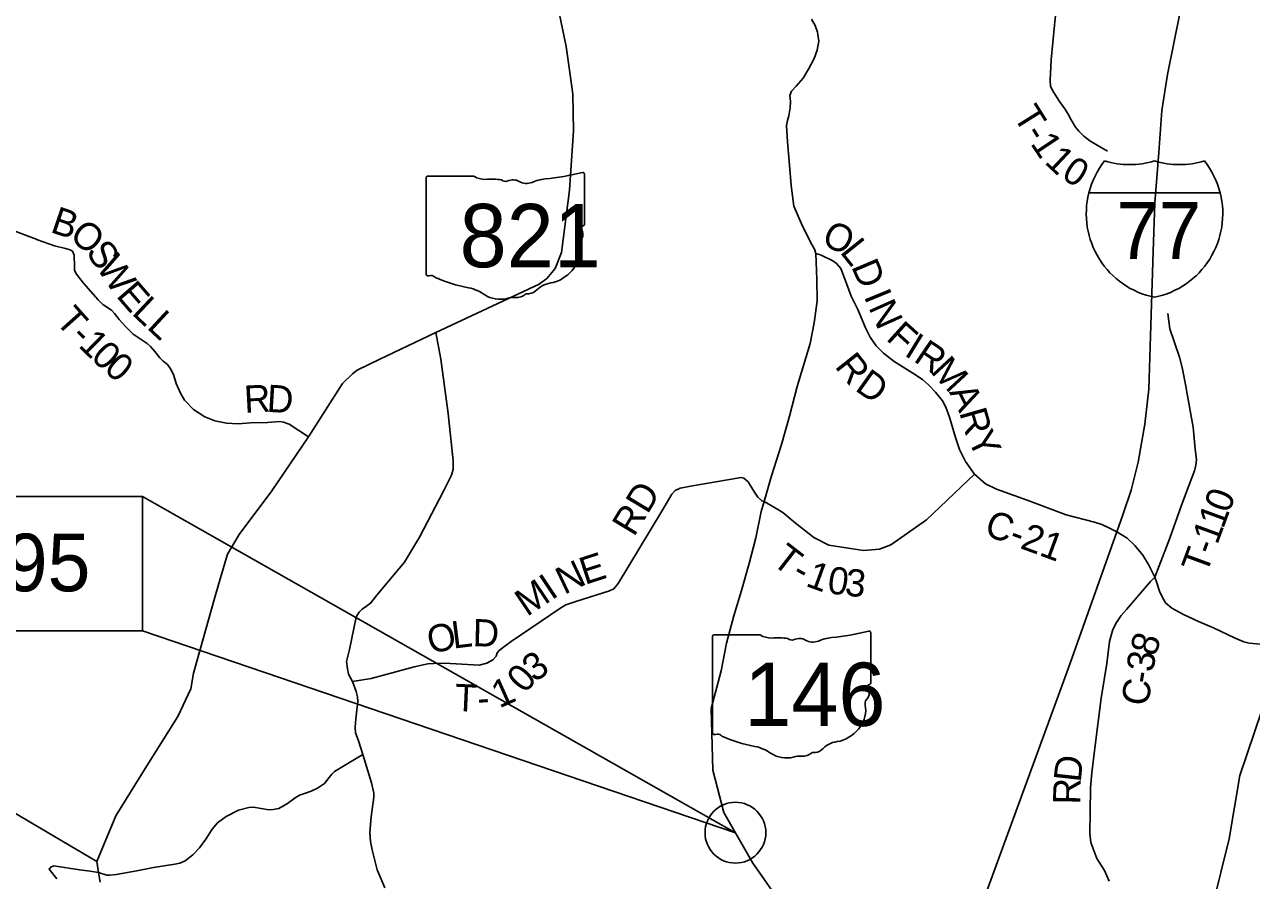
# Model space of a CAD drawing. Extents: x -22 to 431, y -18 to 160.
# Drawn here: x 322.427 to 324.981, y 154.927 to 156.71 of the extents above; entities that cross this region are included whole.
import ezdxf

# ---------------------------------------------------------------- set-up
doc = ezdxf.new("R2010")
doc.units = 0
for name, color, linetype in [('GM_X_Adjacent_County', 7, 'Continuous'), ('GM_X_Adjacent_County_Text', 7, 'Continuous'), ('GM_X_Airport_Location_Class_2', 7, 'Continuous'), ('GM_X_City_Street', 7, 'Continuous'), ('GM_X_City_Street_Text', 7, 'Continuous'), ('GM_X_County_Road', 7, 'Continuous'), ('GM_X_County_ROW', 7, 'Continuous'), ('GM_X_Minor_Lake', 7, 'Continuous'), ('GM_X_Minor_River_Text', 7, 'Continuous'), ('GM_X_Rail_Line', 7, 'Continuous'), ('GM_X_Rail_Line_Text', 7, 'Continuous'), ('GM_X_Section', 7, 'Continuous')]:
    doc.layers.add(name, color=color, linetype=linetype)

msp = doc.modelspace()

# ---------------------------------------------------------------- linework, layer by layer
at = {"layer": 'GM_X_Adjacent_County'}
msp.add_circle((323.9069, 155.0269), 0.0633, dxfattribs=at)
at = {"layer": 'GM_X_Adjacent_County_Text'}
for points in [[(324.0743, 156.2336), (324.0837, 156.2305), (324.11, 156.2181), (324.1175, 156.2127), (324.1265, 156.2024), (324.1379, 156.1712), (324.1482, 156.1446), (324.1615, 156.1168), (324.1774, 156.0783), (324.1874, 156.0593), (324.2001, 156.0413), (324.215, 156.0256), (324.2372, 156.0084), (324.2762, 155.9841), (324.2965, 155.971), (324.3089, 155.9599), (324.3238, 155.9442), (324.3377, 155.9266), (324.3447, 155.9133), (324.3528, 155.8927), (324.3652, 155.8498), (324.3737, 155.8254), (324.3859, 155.7999), (324.4049, 155.774), (324.4278, 155.7536), (324.4507, 155.7424), (324.514, 155.7194), (324.5957, 155.6891), (324.6546, 155.6737), (324.6696, 155.6686), (324.6832, 155.6624), (324.7007, 155.6534), (324.7226, 155.6405), (324.7384, 155.6251), (324.7552, 155.6053), (324.7671, 155.5858), (324.78, 155.5591)], [(323.1766, 154.9118), (323.1612, 154.9492), (323.1507, 154.9912), (323.1471, 155.0086), (323.1455, 155.0276), (323.1483, 155.0598), (323.1537, 155.1008), (323.154, 155.1092), (323.1489, 155.1308), (323.1307, 155.1894), (323.1272, 155.2027), (323.121, 155.2204), (323.1156, 155.2348), (323.1152, 155.2454), (323.1155, 155.2564), (323.1187, 155.283), (323.1205, 155.2993), (323.1197, 155.3099), (323.1173, 155.3209), (323.1096, 155.3421), (323.1015, 155.3568), (323.0993, 155.3684), (323.0971, 155.3836), (323.1031, 155.4086), (323.1174, 155.4755), (323.1189, 155.4797), (323.1231, 155.4861), (323.13, 155.4925), (323.1384, 155.4985), (323.1479, 155.5056), (323.1605, 155.5218), (323.2068, 155.577), (323.2179, 155.5906), (323.2487, 155.6422), (323.2992, 155.7384), (323.3154, 155.7716), (323.3189, 155.7841), (323.3191, 155.8015), (323.3088, 155.9002), (323.2933, 156.0129), (323.2832, 156.0685)], [(324.78, 155.5591), (324.7709, 155.5498), (324.725, 155.4964), (324.7212, 155.492)], [(324.78, 155.5591), (324.7845, 155.547), (324.79, 155.5302), (324.7951, 155.5181), (324.8026, 155.5055), (324.8157, 155.4944), (324.8401, 155.4816), (324.8714, 155.4669), (324.9022, 155.4537), (324.9477, 155.4324), (324.9658, 155.4247), (324.9768, 155.4219), (325.0005, 155.4194), (325.0206, 155.4181), (325.0376, 155.4152), (325.0628, 155.4078), (325.0922, 155.3992), (325.1095, 155.3918), (325.1197, 155.3871), (325.1266, 155.3827), (325.1334, 155.3754), (325.141, 155.3672), (325.1441, 155.3573), (325.1469, 155.3484)], [(324.7212, 155.492), (324.7211, 155.4919), (324.7101, 155.4791), (324.7001, 155.4648), (324.6928, 155.4501), (324.6857, 155.4251), (324.6803, 155.3793), (324.6681, 155.3072), (324.6555, 155.2027), (324.6492, 155.1514), (324.6464, 155.1202), (324.6457, 155.0694), (324.6446, 155.025), (324.6472, 155.0064), (324.6591, 154.9729), (324.6751, 154.9478), (324.6853, 154.9259)]]:
    msp.add_lwpolyline(points, dxfattribs=at)
at = {"layer": 'GM_X_Airport_Location_Class_2'}
for p, q in [((323.2627, 156.3907), (323.2627, 156.1906)), ((323.3625, 156.3941), (323.266, 156.3941)), ((323.5923, 156.2944), (323.5923, 156.3991)), ((323.5923, 156.2944), (323.5923, 156.2944)), ((323.8589, 155.4353), (323.8589, 155.2351)), ((323.9587, 155.4387), (323.8621, 155.4387)), ((324.1885, 155.339), (324.1885, 155.4437)), ((324.1885, 155.339), (324.1885, 155.339))]:
    msp.add_line(p, q, dxfattribs=at)
for centre, major_axis, start_param, end_param in [((323.4749, 156.6669), (0.3495, 0), 4.814394, 5.042369), ((323.5886, 156.3995), (0.00367, 0), 6.141152, 7.989035), ((323.2665, 156.3911), (0.00382, 0), 1.712693, 3.28349), ((323.3855, 156.4173), (0.037, 0), 4.042523, 4.731795), ((323.3977, 156.2818), (0.133, 0), 1.404758, 1.657858), ((323.4279, 156.3921), (0.0107, 0), 3.836095, 5.185415), ((323.4436, 156.369), (0.0222, 0), 0.950623, 2.079405), ((323.4723, 156.4007), (0.0267, 0), 4.081561, 5.145723), ((323.5195, 156.333), (0.0703, 0), 1.699011, 2.107814), ((323.5915, 156.2867), (0.00568, 0), 1.883978, 3.671073), ((323.5553, 156.2735), (0.0341, 0), 5.934695, 6.695948), ((323.5884, 156.294), (0.00393, 0), 5.05454, 6.418171), ((323.4945, 156.2373), (0.0874, 0), 5.101752, 6.440018), ((323.6054, 156.2506), (0.0248, 0), 2.387724, 3.262537), ((323.2665, 156.1901), (0.00385, 0), 3.00124, 4.508301), ((323.2671, 156.2106), (0.0294, 0), 4.665946, 4.897461), ((323.2731, 156.179), (0.0106, 0), 0.519207, 1.627899), ((323.4069, 156.3588), (0.2524, 0), 4.195997, 4.488961), ((323.5313, 156.1344), (0.0479, 0), 1.647645, 2.488434), ((323.3317, 156.1006), (0.079, 0), 0.823519, 1.323587), ((323.4171, 156.178), (0.0501, 0), 4.026481, 4.996735), ((323.4497, 156.163), (0.0267, 0), 4.691044, 5.507374), ((323.4739, 156.1436), (0.00752, 0), 1.147584, 2.315152), ((323.4707, 156.1712), (0.0282, 0), 4.937069, 5.64225), ((323.4461, 156.1088), (0.0412, 0), 1.495662, 1.94098), ((323.8627, 155.4357), (0.00382, 0), 1.712693, 3.28349), ((323.9817, 155.4619), (0.037, 0), 4.042523, 4.731795), ((323.9939, 155.3263), (0.133, 0), 1.404758, 1.657858), ((324.0241, 155.4367), (0.0107, 0), 3.836095, 5.185415), ((324.0398, 155.4136), (0.0222, 0), 0.950623, 2.079405), ((324.1157, 155.3776), (0.0703, 0), 1.699011, 2.107814), ((324.0711, 155.7115), (0.3495, 0), 4.814394, 5.042369), ((324.1848, 155.4441), (0.00367, 0), 6.141152, 7.989035), ((324.0685, 155.4453), (0.0267, 0), 4.081561, 5.145723), ((324.1876, 155.3313), (0.00568, 0), 1.883978, 3.671073), ((324.1515, 155.3181), (0.0341, 0), 5.934695, 6.695948), ((324.1846, 155.3386), (0.00393, 0), 5.05454, 6.418171), ((324.2016, 155.2952), (0.0248, 0), 2.387724, 3.262537), ((324.0907, 155.2818), (0.0874, 0), 5.101752, 6.440018), ((323.8627, 155.2347), (0.00385, 0), 3.00124, 4.508301), ((323.8633, 155.2552), (0.0294, 0), 4.665946, 4.897461), ((323.8693, 155.2236), (0.0106, 0), 0.519207, 1.627899), ((324.0031, 155.4034), (0.2524, 0), 4.195997, 4.488961), ((323.9279, 155.1452), (0.079, 0), 0.823519, 1.323587), ((324.0669, 155.2157), (0.0282, 0), 4.937069, 5.64225), ((324.1275, 155.179), (0.0479, 0), 1.647645, 2.488434), ((324.0133, 155.2226), (0.0501, 0), 4.026481, 4.996735), ((324.0423, 155.1534), (0.0412, 0), 1.495662, 1.94098), ((324.0459, 155.2076), (0.0267, 0), 4.691044, 5.507374), ((324.0701, 155.1882), (0.00752, 0), 1.147584, 2.315152)]:
    msp.add_ellipse(centre, major_axis=major_axis, ratio=0.8, start_param=start_param, end_param=end_param, dxfattribs=at)
at = {"layer": 'GM_X_County_Road'}
for points in [[(322.2859, 156.3326), (322.3093, 156.3223), (322.3564, 156.2995), (322.4031, 156.2816), (322.4456, 156.2652), (322.4498, 156.2636)], [(325.0761, 155.359), (325.0436, 155.342), (325.003, 155.2814), (324.9572, 155.1463), (324.9349, 155.0139), (324.8995, 154.871), (324.8735, 154.8425), (324.8277, 154.8155), (324.7381, 154.7797)]]:
    msp.add_lwpolyline(points, dxfattribs=at)
at = {"layer": 'GM_X_County_ROW'}
for points in [[(322.5772, 154.9665), (322.6164, 155.0623), (322.6775, 155.1606), (322.7457, 155.2688), (322.7732, 155.3262), (322.7784, 155.3589), (322.8237, 155.5196), (322.8349, 155.558), (322.8492, 155.607), (322.8734, 155.648), (322.9418, 155.739), (323.0179, 155.8514), (323.089, 155.9626), (323.1096, 155.9825), (323.1191, 155.99), (323.1662, 156.0134), (323.2832, 156.0685), (323.4979, 156.1698), (323.5144, 156.181), (323.5316, 156.2021), (323.5444, 156.2353), (323.5614, 156.3653), (323.57, 156.4888), (323.5684, 156.5653), (323.5623, 156.6104), (323.5546, 156.6648), (323.5287, 156.7885)], [(324.0654, 156.7216), (324.073, 156.7085), (324.078, 156.6945), (324.0802, 156.676), (324.0772, 156.657), (324.0709, 156.6397), (324.059, 156.6171), (324.048, 156.5986), (324.0334, 156.5819), (324.0236, 156.5718), (324.0203, 156.5625), (324.0212, 156.5497), (324.0209, 156.5369), (324.0179, 156.5203), (324.0155, 156.5104), (324.0134, 156.4997), (324.0152, 156.466), (324.0185, 156.4254), (324.0227, 156.3748), (324.0285, 156.3318), (324.0445, 156.2952), (324.0531, 156.2778), (324.0657, 156.2523), (324.0713, 156.2427), (324.0743, 156.2336), (324.0767, 156.179), (324.0771, 156.1348), (324.0715, 156.0938), (324.0714, 156.0936)], [(324.0714, 156.0936), (324.0708, 156.0888), (324.0622, 156.0459), (324.0356, 155.9561), (324.0193, 155.8944), (324.003, 155.8354), (323.9821, 155.7703), (323.9664, 155.717), (323.9603, 155.6961), (323.9492, 155.641), (323.9355, 155.5877), (323.9195, 155.5314), (323.9034, 155.4785), (323.8886, 155.4214), (323.8775, 155.364), (323.8561, 155.2858), (323.8595, 155.1569), (323.883, 155.0689), (323.9431, 154.9634), (324.0616, 154.7937)], [(322.2699, 155.1481), (322.5772, 154.9665)], [(322.5839, 154.924), (322.5807, 154.944), (322.5772, 154.9665)]]:
    msp.add_lwpolyline(points, dxfattribs=at)
at = {"layer": 'GM_X_Minor_Lake'}
for points in [[(321.422, 155.4474), (322.672, 155.4474), (322.672, 155.7274), (321.422, 155.7274)], [(322.672, 155.7274), (323.9069, 155.0269), (322.672, 155.4474)]]:
    msp.add_lwpolyline(points, close=True, dxfattribs=at)
at = {"layer": 'GM_X_Minor_River_Text'}
for points in [[(324.5715, 156.7092), (324.5721, 156.7159), (324.5743, 156.7347), (324.5696, 156.7449), (324.5651, 156.7484), (324.5455, 156.748), (324.5208, 156.7456), (324.512, 156.7447), (324.4946, 156.738), (324.4445, 156.7376), (324.3683, 156.7897), (324.356, 156.7917), (324.3469, 156.794), (324.3113, 156.8061), (324.2633, 156.8231), (324.2299, 156.8346), (324.2097, 156.8408), (324.2023, 156.8458), (324.1966, 156.8535)], [(324.6813, 156.4468), (324.6598, 156.4588), (324.6448, 156.468), (324.632, 156.4776), (324.6219, 156.488), (324.6148, 156.4964), (324.6059, 156.5116), (324.6, 156.5238), (324.5929, 156.5349), (324.5803, 156.5524), (324.5676, 156.5723), (324.5632, 156.5814), (324.5625, 156.5947), (324.5645, 156.6367), (324.5715, 156.7092)], [(322.4498, 156.2636), (322.4535, 156.2621), (322.4893, 156.2496), (322.5116, 156.2441), (322.5214, 156.241), (322.5262, 156.2383), (322.5303, 156.2299), (322.5308, 156.206), (322.5308, 156.1977), (322.5348, 156.1904), (322.5494, 156.1717), (322.5797, 156.1366), (322.5894, 156.127), (322.6014, 156.1193), (322.6082, 156.1147), (322.6142, 156.1085), (322.6235, 156.0956), (322.6377, 156.0806), (322.653, 156.065), (322.6673, 156.0553), (322.6819, 156.0457), (322.6887, 156.0396), (322.698, 156.0289), (322.7085, 156.0163), (322.7152, 156.0094), (322.7242, 156.0021), (322.7309, 155.9933), (322.7369, 155.9811), (322.7423, 155.9625), (322.7516, 155.9423), (322.7594, 155.9275), (322.7785, 155.9083), (322.8021, 155.8933), (322.8228, 155.8851), (322.847, 155.88), (322.8712, 155.8782), (322.8973, 155.8803), (322.9324, 155.8814), (322.9582, 155.8831), (322.9657, 155.8823), (322.9774, 155.878), (323.0179, 155.8514)], [(324.8451, 155.9532), (324.837, 155.9957), (324.8315, 156.0173), (324.8202, 156.0497), (324.8117, 156.0767), (324.8071, 156.1086)], [(324.78, 155.5591), (324.7894, 155.5826), (324.8111, 155.6403), (324.836, 155.7091), (324.8515, 155.7514), (324.8628, 155.7809), (324.8656, 155.7922), (324.8668, 155.8043), (324.8644, 155.826), (324.8599, 155.8719), (324.8467, 155.9448), (324.8452, 155.9528), (324.8451, 155.9532)], [(323.1096, 155.3421), (323.1482, 155.3481), (323.1997, 155.3618), (323.2377, 155.3724), (323.2665, 155.3786), (323.2786, 155.3796), (323.3012, 155.3798), (323.3734, 155.376), (323.3889, 155.3797), (323.4019, 155.3871), (323.4084, 155.3947), (323.4111, 155.4015), (323.4149, 155.4067), (323.4267, 155.4153), (323.4397, 155.4251), (323.5025, 155.4677), (323.5432, 155.4953), (323.5539, 155.5013), (323.5743, 155.5083), (323.6445, 155.5304), (323.6536, 155.5345), (323.6628, 155.5461), (323.707, 155.6192), (323.7539, 155.6969), (323.7747, 155.7319), (323.7816, 155.7398), (323.7918, 155.7443), (323.8176, 155.7497), (323.9187, 155.7669), (323.9247, 155.7654), (323.9333, 155.7577), (323.9449, 155.7383), (323.9538, 155.7257), (323.9617, 155.7184), (323.9664, 155.717)], [(323.9664, 155.717), (323.988, 155.7041), (324.0057, 155.6941), (324.0315, 155.6722), (324.0702, 155.6419), (324.1017, 155.6257), (324.1738, 155.615), (324.2072, 155.6178), (324.2307, 155.6267), (324.3045, 155.6787), (324.4049, 155.774)], [(322.5807, 154.944), (322.5983, 154.9387), (322.604, 154.9387), (322.6176, 154.9396), (322.6603, 154.9475), (322.6955, 154.9546), (322.7393, 154.9614), (322.7503, 154.9634), (322.7612, 154.968), (322.7774, 154.981), (322.7906, 154.9956), (322.8041, 155.0131), (322.8172, 155.0341), (322.8285, 155.0474), (322.8465, 155.0605), (322.8722, 155.0736), (322.8937, 155.0794), (322.9036, 155.0803), (322.935, 155.0748), (322.9445, 155.0753), (322.9558, 155.0769), (322.9743, 155.088), (322.9901, 155.0995), (322.9992, 155.1053), (323.0094, 155.1084), (323.0234, 155.1135), (323.0366, 155.1193), (323.0509, 155.1296), (323.0606, 155.1418), (323.0663, 155.1487), (323.0723, 155.1544), (323.0859, 155.1629), (323.1307, 155.1894)], [(322.4938, 154.9309), (322.4778, 154.9506), (322.4811, 154.9547), (322.4876, 154.9576), (322.5413, 154.9493), (322.5631, 154.9464), (322.5807, 154.944)]]:
    msp.add_lwpolyline(points, dxfattribs=at)
at = {"layer": 'GM_X_Rail_Line'}
msp.add_lwpolyline([(324.3433, 154.668), (324.3433, 154.668), (324.6003, 155.3703), (324.7007, 155.6534), (324.7133, 155.6889), (324.7311, 155.7403), (324.7457, 155.7986), (324.7593, 155.8776), (324.768, 155.9509), (324.7709, 156.0621), (324.777, 156.2373), (324.7801, 156.3386), (324.7887, 156.4438), (324.7946, 156.5315), (324.8063, 156.6063), (324.8335, 156.7402), (324.8545, 156.8387)], dxfattribs=at)
at = {"layer": 'GM_X_Rail_Line_Text'}
for p, q in [((324.6429, 156.3598), (324.9161, 156.3598)), ((324.9161, 156.3598), (324.6429, 156.3598)), ((324.9161, 156.3598), (324.6429, 156.3598))]:
    msp.add_line(p, q, dxfattribs=at)
for centre, start, end in [((324.815, 156.3162), 141.669, 165.8066), ((324.7276, 156.5961), 253.0091, 286.9909), ((324.8314, 156.5961), 253.0091, 286.9909), ((324.744, 156.3162), 14.1934, 38.331), ((324.815, 156.3162), 165.8066, 258.463), ((324.744, 156.3162), 281.537, 14.1934)]:
    msp.add_arc(centre, 0.1776, start, end, dxfattribs=at)

# ---------------------------------------------------------------- texts
at = {"layer": 'GM_X_Airport_Location_Class_2'}
for s, p in [('821', (323.3325, 156.2047)), ('146', (323.9252, 155.2492))]:
    msp.add_text(s, height=0.13184, dxfattribs=at).set_placement(p)
at = {"layer": 'GM_X_City_Street'}
for s, height, rotation, p in [('O', 0.0568, 333.2183, (324.0833, 156.2547)), ('L', 0.0568, 308.7421, (324.123, 156.2362)), ('D', 0.0568, 293.013, (324.1475, 156.2065)), ('I', 0.0568, 292.2949, (324.1736, 156.1445)), ('N', 0.0568, 294.0168, (324.1832, 156.1212)), ('F', 0.0568, 317.8384, (324.2186, 156.0548)), ('I', 0.0568, 328.6139, (324.2563, 156.0221)), ('R', 0.0568, 325.7882, (324.2756, 156.0103)), ('R', 0.0568, 308.5227, (324.1123, 155.9978)), ('M', 0.0568, 312.863, (324.3116, 155.9863)), ('D', 0.0568, 324.605, (324.1537, 155.9496)), ('A', 0.0568, 296.6433, (324.3512, 155.9446)), ('R', 0.0568, 286.0151, (324.3726, 155.9025)), ('Y', 0.0568, 295.5868, (324.3891, 155.8479)), ('C-21', 0.05682, 339.725, (324.4224, 155.6479)), ('8', 0.0568, 72.1493, (324.7811, 155.3919)), ('3', 0.0568, 82.7498, (324.7773, 155.3599)), ('-', 0.0568, 80.9845, (324.7733, 155.335)), ('C', 0.0568, 80.5787, (324.7656, 155.2885)), ('D', 0.0568, 83.7366, (324.6257, 155.1306)), ('R', 0.0568, 88.9774, (324.6249, 155.0853))]:
    msp.add_text(s, height=height, rotation=rotation, dxfattribs=at).set_placement(p)
at = {"layer": 'GM_X_City_Street_Text'}
for s, height, rotation, p in [('T', 0.0568, 302.0376, (324.484, 156.5197)), ('1', 0.0568, 303.6961, (324.5199, 156.4624)), ('-', 0.0568, 302.2305, (324.5066, 156.4835)), ('1', 0.0568, 316.8619, (324.5485, 156.4224)), ('0', 0.0568, 327.46, (324.5831, 156.3915)), ('B', 0.0568, 341.1824, (322.4783, 156.2786)), ('O', 0.0568, 319.652, (322.5176, 156.2663)), ('S', 0.0568, 303.7981, (322.553, 156.237)), ('W', 0.0568, 304.1143, (322.5745, 156.2049)), ('E', 0.0568, 310.8394, (322.6158, 156.1446)), ('T', 0.0568, 311.7407, (322.489, 156.0918)), ('L', 0.0568, 316.7332, (322.648, 156.1079)), ('L', 0.0568, 317.2275, (322.6794, 156.0784)), ('-', 0.0568, 315.4272, (322.52, 156.0572)), ('1', 0.0568, 315.6579, (322.5368, 156.0406)), ('0', 0.0568, 316.6269, (322.5626, 156.0154)), ('0', 0.0568, 318.7464, (322.5898, 155.9899)), ('R', 0.0568, 2.9207, (322.8851, 155.9012)), ('D', 0.0568, 356.6686, (322.9301, 155.9036)), ('RD', 0.05682, 58.8678, (323.6955, 155.6416)), ('0', 0.0568, 69.3148, (324.9344, 155.6907)), ('1', 0.0568, 69.7381, (324.9223, 155.6579)), ('1', 0.0568, 69.8039, (324.9102, 155.6251)), ('E', 0.0568, 18.0162, (323.5935, 155.5428)), ('T', 0.0568, 322.1521, (323.9803, 155.5882)), ('T', 0.0568, 69.8206, (324.8875, 155.5633)), ('-', 0.0568, 69.8121, (324.9022, 155.6032)), ('N', 0.0568, 25.4099, (323.5502, 155.5221)), ('1', 0.0568, 339.9706, (324.051, 155.5414)), ('I', 0.0568, 33.6836, (323.524, 155.5102)), ('-', 0.0568, 330.6706, (324.0215, 155.557)), ('0', 0.0568, 352.1052, (324.0965, 155.5262)), ('3', 0.0568, 353.9545, (324.1332, 155.5212)), ('M', 0.0568, 33.9563, (323.4729, 155.4758)), ('O', 0.0568, 13.5123, (323.2724, 155.3987)), ('L', 0.0568, 7.1543, (323.3194, 155.4101)), ('D', 0.0568, 358.5501, (323.3593, 155.4153)), ('3', 0.0568, 35.4282, (323.4889, 155.3388)), ('0', 0.0568, 48.1782, (323.4681, 155.315)), ('T', 0.0568, 357.4192, (323.3214, 155.2804)), ('1', 0.0568, 24.044, (323.4152, 155.2854)), ('-', 0.0568, 4.0323, (323.371, 155.2786))]:
    msp.add_text(s, height=height, rotation=rotation, dxfattribs=at).set_placement(p)
at = {"layer": 'GM_X_Rail_Line_Text'}
msp.add_text('77', height=0.11837, dxfattribs=at).set_placement((324.7005, 156.2222))
at = {"layer": 'GM_X_Section'}
msp.add_text('NOB-146-1.95', height=0.12, dxfattribs=at).set_placement((321.5292, 155.5297))

doc.saveas('drawing.dxf')
